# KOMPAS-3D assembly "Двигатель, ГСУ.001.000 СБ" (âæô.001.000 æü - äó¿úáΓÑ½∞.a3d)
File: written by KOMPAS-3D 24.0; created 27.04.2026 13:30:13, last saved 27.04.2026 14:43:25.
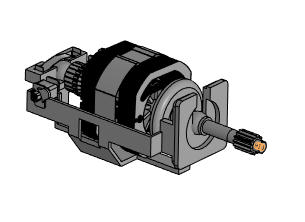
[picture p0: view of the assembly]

Document properties: Автор: User7; Полное имя файла: C:\Users\User7\Desktop\Двигатель мясорубки\ГСУ.001.000 СБ - Двигатель.a3d

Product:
- Component [assembly]: Ротор  | designation ГСУ.001.100 СБ  | qty 1  | pos. 1  | Масса: 0.220757; Автор: User7; source file: ГСУ.001.100 СБ - Ротор.a3d
- Component [detail]: Рама двигателя  | designation ГСУ.001.001  | qty 1  | pos. 4  | Масса: 0.218408; Автор: User7; source file: ГСУ.001.001 - Рама двигателя.m3d
- Component [detail]: Основание стартера  | designation ГСУ.001.002  | qty 2  | pos. 5  | Масса: 0.054294; Автор: User7; source file: ГСУ.001.002 - Основание стартера.m3d
- Component [detail]: Держатель щеток  | designation ГСУ.001.003  | qty 2  | pos. 6  | Масса: 0.006286; Автор: User7; source file: ГСУ.001.003 - Держатель щеток.m3d
- Component [detail]: Щетка  | designation ГСУ.001.004  | qty 2  | pos. 7  | Масса: 0.001131; Автор: User7; source file: ГСУ.001.004 - Щетка.m3d
- Component [detail]: Пластина  | designation ГСУ.001.005  | qty 2  | pos. 8  | Масса: 0.002713; Автор: User7; source file: ГСУ.001.005 - Пластина.m3d
- Component [detail]: Уплотнитель  | designation ГСУ.001.007  | qty 2  | pos. 10  | Масса: 0.000505; Автор: User7; source file: ГСУ.001.007 - Уплотнитель.m3d
- Component [detail]: Пружина  | designation ГСУ.001.008  | qty 2  | pos. 11  | Масса: 0.000147; Автор: User7; source file: ГСУ.001.008 - Пружина.m3d
- Component [detail]: Обмотка  | designation ГСУ.001.009  | qty 2  | pos. 12  | Масса: 0.009785; Автор: User7; source file: ГСУ.001.009 - Обмотка.m3d
- Component [detail]: Пластина держателя пружин  | designation ГСУ.001.011  | qty 2  | pos. 13  | Масса: 0.000005; Автор: User7; source file: ГСУ.001.011 - Пластина держателя пружин.m3d
- Component [detail]: Держатель стартера  | designation ГСУ.001.012  | qty 1  | pos. 14  | Масса: 0.003518; Автор: User7; source file: ГСУ.001.012 - Держатель стартера.m3d
- Component [detail]: Пластина держателя втулок ротора  | designation ГСУ.001.013  | qty 1  | pos. 15  | Масса: 0.000666; Автор: User7; source file: ГСУ.001.013 - Пластина держателя втулок ротора.m3d
- Component [detail]: Пластинка  | designation ГСУ.001.006  | qty 2  | pos. 9  | Масса: 0.002129; Автор: User7; source file: ГСУ.001.006 - Пластинка.m3d
- Part/product: Двигатель  | designation ГСУ.001.000 СБ
    Масса: 0.59734

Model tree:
1. Массив по концентрической сетке:1  (with: Грань.Элемент выдавливания:1, Ребро.Элемент выдавливания:6, Ребро.Элемент выдавливания:7, Ребро.Обечайка:1, Ребро.Элемент выдавливания:2, Грань.Элемент выдавливания:7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)  (labels: Ребро.Тело 1.Экземпляр ( 64, 1 ); Грань.Тело 1.Экземпляр ( 64, 1 ); Вершина.Тело 1.Экземпляр ( 64, 1 ))  (2 pattern instances)
     Шаг 2 = 360; Ориентация = 2; Ориентация = 2; Ориентация = 2; Расстояние = 5; Ориентация = 2; Ориентация = 2; Ориентация = 2; Ориентация = 2; Ориентация = 2; Ориентация = 2; Ориентация = 2

Referenced files in C:\Users\User7\Desktop\Двигатель мясорубки\: ГСУ.001.100 СБ - Ротор.a3d, ГСУ.001.001 - Рама двигателя.m3d, ГСУ.001.002 - Основание стартера.m3d, ГСУ.001.003 - Держатель щеток.m3d, ГСУ.001.004 - Щетка.m3d, ГСУ.001.005 - Пластина.m3d, ГСУ.001.007 - Уплотнитель.m3d, ГСУ.001.008 - Пружина.m3d, ГСУ.001.009 - Обмотка.m3d, ГСУ.001.011 - Пластина держателя пружин.m3d, ГСУ.001.012 - Держатель стартера.m3d, ГСУ.001.013 - Пластина держателя втулок ротора.m3d, ГСУ.001.006 - Пластинка.m3d
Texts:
  Точка начала. Х
  Точка начала. Y
  Точка начала. Z
  ГСУ.001.000 СБ
  ГСУ.001.100 СБ Ротор
  ГСУ.001.001 Рама двигателя
  ГСУ.001.002 Основание стартера (1)
  ГСУ.001.003 Держатель щеток (1)
  ГСУ.001.004 Щетка (1)
  ГСУ.001.005 Пластина (1)
  ГСУ.001.007 Уплотнитель (1)
  ГСУ.001.008 Пружина (1)
  ГСУ.001.009 Обмотка (1)
  ГСУ.001.011 Пластина держателя пружин (1)
  ГСУ.001.012 Держатель стартера
  ГСУ.001.002 Основание стартера (2)
  ГСУ.001.003 Держатель щеток (2)
  ГСУ.001.013 Пластина держателя втулок ротора
  ГСУ.001.007 Уплотнитель (2)
  ГСУ.001.006 Пластинка (1)
  ГСУ.001.006 Пластинка (2)
  ГСУ.001.004 Щетка (2)
  ГСУ.001.009 Обмотка (2)
  ГСУ.001.005 Пластина (2)
  ГСУ.001.008 Пружина (2)
  ГСУ.001.011 Пластина держателя пружин (2)
  Плоскость ZX.Начало координат
  Плоскость ZY.Начало координат
  Плоскость XY.Начало координат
